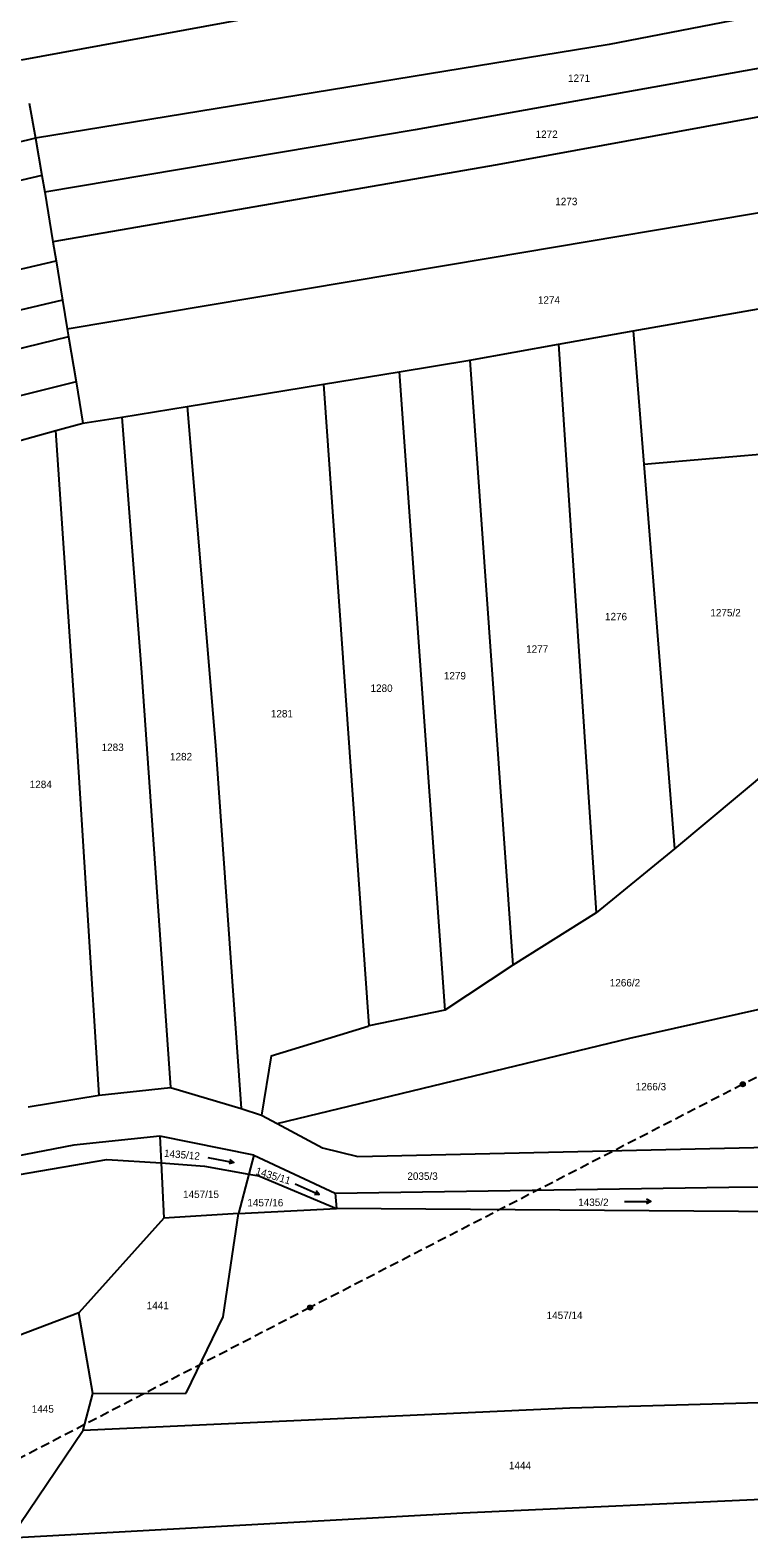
# Model space of a CAD drawing. Extents: x -820420 to -815896, y -1105820 to -1103643.
# Drawn here: x -818588.7 to -818424.2, y -1104571.2 to -1104226.1 of the extents above; entities that cross this region are included whole.
import ezdxf
from ezdxf.enums import TextEntityAlignment as Align

# ---------------------------------------------------------------- set-up
doc = ezdxf.new("R2010")
doc.units = 0
doc.header["$LTSCALE"] = 0.68
doc.linetypes.add('MEDIUM_DASHED', pattern=[4.5, 3, -1.5])
for name, color, linetype, lineweight in [('1', 7, 'Continuous', 25), ('3', 7, 'Continuous', 25), ('6', 7, 'Continuous', 25)]:
    doc.layers.add(name, color=color, linetype=linetype, lineweight=lineweight)
doc.layers.add('2', color=7, linetype='Continuous')

msp = doc.modelspace()

# ---------------------------------------------------------------- linework, layer by layer
at = {"layer": '1'}
for p, q in [((-818590.61, -1104232.92), (-818440.54, -1104205.32)), ((-818390.01, -1104216.65), (-818456.17, -1104229.41)), ((-818456.17, -1104229.41), (-818587.46, -1104250.86)), ((-818420.8, -1104234.69), (-818500.54, -1104248.93)), ((-818377.99, -1104237.98), (-818481.8, -1104256.97)), ((-818588.88, -1104242.82), (-818587.46, -1104250.86)), ((-818587.46, -1104250.86), (-818709.19, -1104280.06)), ((-818587.46, -1104250.86), (-818585.97, -1104259.37)), ((-818500.54, -1104248.93), (-818585.3, -1104263.22)), ((-818481.8, -1104256.97), (-818583.45, -1104274.57)), ((-818585.97, -1104259.37), (-818679.59, -1104281.34)), ((-818585.97, -1104259.37), (-818585.3, -1104263.22)), ((-818483.36, -1104278.25), (-818386.79, -1104261.94)), ((-818585.3, -1104263.22), (-818583.45, -1104274.57)), ((-818583.45, -1104274.57), (-818582.74, -1104278.91)), ((-818659.13, -1104296.69), (-818582.74, -1104278.91)), ((-818582.74, -1104278.91), (-818581.27, -1104287.89)), ((-818580.2, -1104294.46), (-818483.36, -1104278.25)), ((-818450.63, -1104294.92), (-818391.36, -1104284.55)), ((-818581.27, -1104287.89), (-818737.19, -1104325.09)), ((-818581.27, -1104287.89), (-818580.2, -1104294.46)), ((-818579.9, -1104296.28), (-818733.44, -1104333.89)), ((-818580.2, -1104294.46), (-818579.9, -1104296.28)), ((-818579.9, -1104296.28), (-818578.16, -1104306.63)), ((-818467.74, -1104297.97), (-818450.63, -1104294.92)), ((-818488.01, -1104301.69), (-818467.74, -1104297.97)), ((-818467.74, -1104297.97), (-818459.12, -1104428.1)), ((-818504.18, -1104304.31), (-818488.01, -1104301.69)), ((-818488.01, -1104301.69), (-818478.24, -1104440.11)), ((-818578.16, -1104306.63), (-818732.45, -1104345.11)), ((-818578.16, -1104306.63), (-818576.59, -1104316.06)), ((-818521.53, -1104307.14), (-818504.18, -1104304.31)), ((-818504.18, -1104304.31), (-818493.75, -1104450.43)), ((-818552.72, -1104312.22), (-818521.53, -1104307.14)), ((-818521.53, -1104307.14), (-818511.16, -1104454.01)), ((-818567.69, -1104314.66), (-818552.72, -1104312.22)), ((-818552.72, -1104312.22), (-818546.25, -1104389.83)), ((-818582.79, -1104317.78), (-818576.59, -1104316.06)), ((-818576.59, -1104316.06), (-818567.69, -1104314.66)), ((-818567.69, -1104314.66), (-818563.21, -1104373.13)), ((-818600.75, -1104322.76), (-818582.79, -1104317.78)), ((-818578.21, -1104385.02), (-818582.79, -1104317.78)), ((-818448.25, -1104325.45), (-818400.48, -1104321.34)), ((-818563.21, -1104373.13), (-818556.54, -1104468.09)), ((-818572.83, -1104469.88), (-818578.21, -1104385.02)), ((-818546.25, -1104389.83), (-818540.37, -1104472.93)), ((-818419, -1104394.95), (-818441.21, -1104413.5)), ((-818441.21, -1104413.5), (-818459.12, -1104428.1)), ((-818459.12, -1104428.1), (-818478.24, -1104440.11)), ((-818478.24, -1104440.11), (-818493.75, -1104450.43)), ((-818451.46, -1104456.83), (-818408.15, -1104447.11)), ((-818493.75, -1104450.43), (-818511.16, -1104454.01)), ((-818533.54, -1104460.86), (-818511.3, -1104454.04)), ((-818511.16, -1104454.01), (-818511.3, -1104454.04)), ((-818532.16, -1104476.34), (-818451.46, -1104456.83)), ((-818533.54, -1104460.86), (-818535.72, -1104474.44)), ((-818572.83, -1104469.88), (-818556.54, -1104468.09)), ((-818556.54, -1104468.09), (-818540.37, -1104472.93)), ((-818589.15, -1104472.5), (-818572.83, -1104469.88)), ((-818540.37, -1104472.93), (-818535.72, -1104474.44)), ((-818535.72, -1104474.44), (-818532.16, -1104476.34)), ((-818558.96, -1104479.27), (-818578.68, -1104481.28)), ((-818558.96, -1104479.27), (-818558.71, -1104485.38)), ((-818537.47, -1104483.6), (-818558.96, -1104479.27)), ((-818532.16, -1104476.34), (-818521.77, -1104481.95)), ((-818578.68, -1104481.28), (-818604.12, -1104486.18)), ((-818521.77, -1104481.95), (-818513.64, -1104483.89)), ((-818513.64, -1104483.89), (-818403.58, -1104481.37)), ((-818599.86, -1104489.52), (-818571.12, -1104484.6)), ((-818571.12, -1104484.6), (-818558.71, -1104485.38)), ((-818558.71, -1104485.38), (-818558.07, -1104497.98)), ((-818558.71, -1104485.38), (-818548.77, -1104486.14)), ((-818548.77, -1104486.14), (-818538.62, -1104487.93)), ((-818537.47, -1104483.6), (-818538.62, -1104487.93)), ((-818537.47, -1104483.6), (-818518.86, -1104492.33)), ((-818538.62, -1104487.93), (-818541.02, -1104496.96)), ((-818538.62, -1104487.93), (-818536.31, -1104488.34)), ((-818536.31, -1104488.34), (-818518.56, -1104495.77)), ((-818518.86, -1104492.33), (-818428.81, -1104490.91)), ((-818518.86, -1104492.33), (-818518.56, -1104495.77)), ((-818428.81, -1104490.91), (-818402.92, -1104490.85)), ((-818541.02, -1104496.96), (-818518.56, -1104495.77)), ((-818401.41, -1104496.65), (-818518.56, -1104495.77)), ((-818544.51, -1104520.62), (-818541.02, -1104496.96)), ((-818577.49, -1104519.71), (-818598.07, -1104527.44)), ((-818574.35, -1104538.17), (-818577.49, -1104519.71)), ((-818552.97, -1104538.04), (-818544.51, -1104520.62)), ((-818576.5, -1104546.56), (-818574.35, -1104538.17)), ((-818574.35, -1104538.17), (-818552.97, -1104538.04)), ((-818576.5, -1104546.56), (-818465.14, -1104541.42)), ((-818465.14, -1104541.42), (-818389.39, -1104539.29)), ((-818593.15, -1104571.18), (-818576.5, -1104546.56)), ((-818489.62, -1104565.43), (-818387.71, -1104560.84)), ((-818593.15, -1104571.18), (-818489.62, -1104565.43))]:
    msp.add_line(p, q, dxfattribs=at)
for points in [[(-818450.63, -1104294.92), (-818448.25, -1104325.45), (-818441.21, -1104413.5)], [(-818541.02, -1104496.96), (-818558.07, -1104497.98), (-818577.49, -1104519.71)]]:
    msp.add_lwpolyline(points, dxfattribs=at)
at = {"layer": '3'}
for p, q in [((-818542.08, -1104485.264), (-818543.135, -1104485.57)), ((-818522.527, -1104492.625), (-818523.624, -1104492.686)), ((-818446.653, -1104494.199), (-818447.63, -1104494.7))]:
    msp.add_line(p, q, dxfattribs=at)
for points in [[(-818547.97, -1104484.119), (-818542.08, -1104485.264), (-818542.943, -1104484.585)], [(-818528.008, -1104490.185), (-818522.527, -1104492.625), (-818523.216, -1104491.769)], [(-818452.653, -1104494.199), (-818446.653, -1104494.199), (-818447.63, -1104493.697)]]:
    msp.add_lwpolyline(points, dxfattribs=at)
at = {"layer": '6', "linetype": 'MEDIUM_DASHED'}
for p, q in [((-818329.14, -1104419.82), (-818425.57, -1104467.38)), ((-818425.57, -1104467.38), (-818524.6, -1104518.47)), ((-818524.6, -1104518.47), (-818601.59, -1104558.46))]:
    msp.add_line(p, q, dxfattribs=at)
at = {"layer": '6'}
for centre, radius in [((-818425.5734, -1104467.3799), 0.5), ((-818425.5734, -1104467.3799), 0.4), ((-818425.5734, -1104467.3799), 0.3), ((-818425.5734, -1104467.3799), 0.2), ((-818425.5734, -1104467.3799), 0.1), ((-818524.6034, -1104518.4699), 0.5), ((-818524.6034, -1104518.4699), 0.4), ((-818524.6034, -1104518.4699), 0.3), ((-818524.6034, -1104518.4699), 0.2), ((-818524.6034, -1104518.4699), 0.1)]:
    msp.add_circle(centre, radius, dxfattribs=at)

# ---------------------------------------------------------------- texts
at = {"layer": '2'}
for s, p in [('1271', (-818463.04, -1104237.975)), ('1272', (-818470.47, -1104250.795)), ('1273', (-818465.96, -1104266.185)), ('1274', (-818469.94, -1104288.735)), ('1275/2', (-818429.52, -1104360.295)), ('1276', (-818454.59, -1104361.185)), ('1277', (-818472.63, -1104368.615)), ('1280', (-818508.24, -1104377.575)), ('1279', (-818491.46, -1104374.725)), ('1281', (-818531.05, -1104383.415)), ('1283', (-818569.78, -1104391.105)), ('1282', (-818554.13, -1104393.235)), ('1284', (-818586.23, -1104399.595)), ('1266/2', (-818452.54, -1104444.985)), ('1266/3', (-818446.6, -1104468.765)), ('1457/15', (-818549.559, -1104493.405)), ('1435/2', (-818459.77, -1104495.235)), ('1457/16', (-818534.839, -1104495.315)), ('1441', (-818559.46, -1104518.865)), ('1457/14', (-818466.359, -1104521.105)), ('1445', (-818585.76, -1104542.525)), ('1444', (-818476.57, -1104555.475))]:
    msp.add_text(s, height=1.7, dxfattribs=at).set_placement(p, align=Align.CENTER)
for s, rotation, p in [('1435/12', 355, (-818553.9891, -1104484.3264)), ('1435/11', 343, (-818533.2765, -1104489.1245))]:
    msp.add_text(s, height=1.7, rotation=rotation, dxfattribs=at).set_placement(p, align=Align.CENTER)
msp.add_text('2035/3', height=1.7, dxfattribs=at).set_placement((-818502.34, -1104489.245))

doc.saveas('drawing.dxf')
